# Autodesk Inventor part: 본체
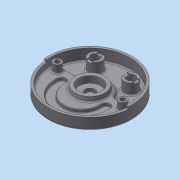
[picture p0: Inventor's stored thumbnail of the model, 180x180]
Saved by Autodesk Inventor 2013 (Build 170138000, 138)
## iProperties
Created: 2015-04
Part Number: 본체
Material: 일반
Document SubType Name: Modeling
Designer: Administrator
Density: 1 g/cm^3
Author: Administrator
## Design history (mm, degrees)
sketch "스케치1"
  geometry: C1 r 95 at (0, 0); 1 further point
  constraints: 1 centre point, 1 coincident
  dimensions: "d0" = 190 diameter of C1
extrude "돌출1" new body sketch "스케치1" distance "d1" = 32; taper "d2" = 0 deg
sketch "스케치2"
  geometry: L1 (-89.196, 12)-(-40.249, 12); L2 (40.249, 12)-(89.196, 12); C1 r 95 at (0, 0) reference; A1 r 90 centre (0, 0) between (89.196, 12) and (-89.196, 12); A2 r 42 centre (0, 0) between (40.249, 12) and (-40.249, 12)
  constraints: 4 end point, 4 point on circle, 2 centre point, 2 coincident, 2 horizontal
  dimensions: "d3" = 180 diameter of A1; "d4" = 84 diameter of A2; "d6" = 12 vertical distance of C1.centre L1.end; "d7" = 12 vertical distance of L2.end C1.centre
extrude "돌출2" cut sketch "스케치2" distance "d8" = 25; taper "d9" = 0 deg
fillet "모깎기1" dims "d10" = 10
sketch "스케치3"
  geometry: L1 (-47.117, 12)-(-76.916, 12) reference; L2 (76.916, 12)-(47.117, 12) reference; C1 r 95 at (0, 0) reference; C2 r 90 at (0, 0); A1 r 10 centre (-76.916, 22) between (-86.53, 24.75) and (-76.916, 12) reference; A2 r 90 centre (0, 0) between (86.53, 24.75) and (-86.53, 24.75) reference; A3 r 10 centre (76.916, 22) between (76.916, 12) and (86.53, 24.75) reference; A4 r 10 centre (47.117, 22) between (38.056, 17.769) and (47.117, 12) reference; A5 r 42 centre (0, 0) between (38.056, 17.769) and (-38.056, 17.769) reference; A6 r 10 centre (-47.117, 22) between (-47.117, 12) and (-38.056, 17.769) reference
  constraints: 1 centre point, 1 coincident
  dimensions: "d11" = 180 diameter of C2
extrude "돌출3" cut sketch "스케치3" distance "d12" = 18; taper "d13" = 0 deg
sketch "스케치6"
  geometry: C1 r 35 at (0, 0); A1 r 42 centre (0, 0) between (38.056, 17.769) and (-38.056, 17.769) reference
  constraints: 1 centre point, 1 coincident
  dimensions: "d34" = 70 diameter of C1
extrude "돌출4" join sketch "스케치6" distance "d35" = 10; taper "d36" = -10 deg
sketch "스케치7"
  geometry: C1 r 33.237 at (0, 0) reference; C2 r 25 at (0, 0)
  constraints: 1 centre point, 1 coincident
  dimensions: "d37" = 50 diameter of C2
extrude "돌출5" cut sketch "스케치7" distance "d38" = 15; taper "d39" = 0 deg
sketch "스케치8"
  geometry: C1 r 25 at (0, 0) reference; C2 r 11.5 at (0, 0)
  constraints: 1 centre point, 1 coincident
  dimensions: "d40" = 23 diameter of C2
extrude "돌출6" cut sketch "스케치8" stored distance "d41" = 15; taper "d42" = 0 deg
sketch "스케치9"
  geometry: C1 r 15 at (-40, 52); C2 r 15 at (40, 52); A1 r 90 centre (0, 0) between (86.53, 24.75) and (-86.53, 24.75) reference
  constraints: 2 centre point, 1 horizontal alignment
  dimensions: "d43" = 30 diameter of C1; "d44" = 30 diameter of C2; "d45" = 80 distance of C2.centre C1.centre; "d46" = 40 horizontal distance of C1.centre A1.centre; "d47" = 52 vertical distance of A1.centre C2.centre
extrude "돌출7" join sketch "스케치9" distance "d48" = 25; taper "d49" = 0 deg
sketch "스케치10"
  geometry: C1 r 15 at (0, 0) reference; C2 r 15 at (80, 0) reference; C3 r 10 at (0, 0); C4 r 10 at (80, 0); 1 further point
  constraints: 2 centre point, 2 coincident
  dimensions: "d50" = 20 diameter of C3; "d51" = 20 diameter of C4
extrude "돌출8" cut sketch "스케치10" stored distance "d52" = 25; taper "d53" = 0 deg
sketch "스케치11"
  geometry: C1 r 35 at (0, 0) reference; C2 r 9 at (-74, 0); C3 r 9 at (74, 0)
  constraints: 2 centre point, 2 horizontal alignment
  dimensions: "d54" = 18 diameter of C2; "d55" = 18 diameter of C3; "d56" = 148 distance of C3.centre C2.centre; "d57" = 74 distance of C2.centre C1.centre
extrude "돌출9" join sketch "스케치11" distance "d58" = 18; taper "d59" = 0 deg
sketch "스케치12"
  geometry: C1 r 9 at (-74, 0) reference; C2 r 10 at (40, 52) reference; C3 r 10 at (-40, 52) reference; C4 r 11.5 at (0, 0) reference; C5 r 95 at (0, 0) reference; C6 r 9 at (74, 0) reference; 2 further points
  constraints: 2 coincident
hole "구멍1" sketch "스케치12" at (-74, 0), (74, 0) diameter "d60" = 11; stored, may be unused: countersink angle "d64" = 90 deg, drill point angle "d66" = 0 deg; dims "d61" = 6, "d62" = 18, "d63" = 11, "d65" = 8
sketch "스케치13"
  geometry: L1 (-76.916, 12)-(-47.117, 12) reference; L2 (-59, -19)-(-41, -19); L3 (41, -19)-(59, -19); L4 (41, -19)-(41, -14); L5 (59, -19)-(59, -14); L6 (41, -14)-(59, -14); L7 (-59, -19)-(-59, -14); L8 (-41, -19)-(-41, -14); L9 (-41, -14)-(-59, -14); C1 r 35 at (0, 0) reference; A1 r 59 centre (0, -19) between (-59, -19) and (59, -19); A2 r 41 centre (0, -19) between (-41, -19) and (41, -19); A3 r 9 centre (50, -14) between (59, -14) and (41, -14); A4 r 9 centre (-50, -14) between (-41, -14) and (-59, -14)
  constraints: 16 end point, 8 point on circle, 4 centre point, 4 tangent, 2 midpoint, 2 parallel, 1 coincident, 1 collinear, 1 perpendicular, 1 vertical alignment
  dimensions: "d70" = 82 diameter of A2; "d72" = 19 distance of A1.centre C1.centre; "d75" = 5 distance of L4.end L3.start; "d76" = 5 distance of L5.end L3.end; "d79" = 59 radius of A1; "d80" = 5 distance of L7.end L2.start; "d81" = 5 distance of L8.end L2.end
extrude "돌출10" cut sketch "스케치13" distance "d83" = 7; taper "d84" = 0 deg
sketch "스케치16"
  geometry: L1 (0, 0)-(-112.328, 0); L2 (-89.658, -7.844)-(-94.638, -8.28); L3 (0, 0)-(105.461, 0); L4 (89.658, -7.844)-(94.638, -8.28); A1 r 95 centre (0, 0) between (-94.638, -8.28) and (94.638, -8.28) reference; A2 r 90 centre (0, 0) between (-89.658, -7.844) and (89.658, -7.844) reference
  constraints: 8 end point, 4 point on circle, 1 collinear, 1 horizontal
  dimensions: "d90" = 5 deg angle of L2 L1; "d91" = 5 deg angle of L4 L3; "d92" = 4.98097 horizontal distance of L2.start L2.end; "d93" = 4.98097 horizontal distance of L4.start L4.end
extrude "돌출12" cut sketch "스케치16" distance "d94" = 5; taper "d95" = 0 deg
fillet "모깎기2" dims "d96" = 0.3
fillet "모깎기3" dims "d97" = 5
chamfer "모따기1" distance "d99" = 1; stored, may be unused: second distance "d100" = 2, angle "d101" = 45 deg
fillet "모깎기5" dims "d102" = 1
fillet "모깎기6" dims "d103" = 3
chamfer "모따기2" distance "d104" = 1; stored, may be unused: second distance "d105" = 2, angle "d106" = 45 deg
sketch "스케치17"
  geometry: L1 (-6, 13.748)-(-6, 8); L2 (-6, -8)-(-6, -13.748); L3 (6, 13.748)-(6, 8); L4 (6, -8)-(6, -13.748); L5 (66.252, 6)-(72, 6); L6 (88, 6)-(93.748, 6); L7 (66.252, -6)-(72, -6); L8 (88, -6)-(93.748, -6); A1 r 10 centre (0, 0) between (-6, 8) and (-6, -8) reference; A2 r 15 centre (0, 0) between (-6, -13.748) and (6, -13.748) reference; A3 r 15 centre (80, 0) between (66.252, -6) and (66.252, 6) reference; A4 r 10 centre (80, 0) between (72, 6) and (88, 6) reference; 1 further point
  constraints: 16 end point, 16 point on circle, 12 parallel, 2 perpendicular, 2 vertical, 1 horizontal alignment, 1 vertical alignment
  dimensions: "d110" = 12 distance of L7.start L5.start; "d112" = 12 distance of L3.start L1.start
extrude "돌출13" cut sketch "스케치17" distance "d113" = 3; taper "d114" = 0 deg
fillet "모깎기7" dims "d115" = 3
sketch "스케치18"
  geometry: L1 (0, 0)-(0, -85.954); L2 (-36.062, -36.062)-(-50.912, -50.912); L3 (36.062, -36.062)-(50.912, -50.912); C1 r 12.5 at (0, 0) reference; A1 r 51 centre (0, 0) between (-36.062, -36.062) and (36.062, -36.062); A2 r 72 centre (0, 0) between (-50.912, -50.912) and (50.912, -50.912)
  constraints: 6 end point, 4 point on circle, 2 centre point, 2 coincident, 1 vertical
  dimensions: "d117" = 102 diameter of A1; "d120" = 72 radius of A2; "d121" = 21 distance of L3.start L3.end; "d122" = 21 distance of L2.start L2.end; "d123" = 45 deg angle of L1 L2; "d124" = 45 deg angle of L3 L1
extrude "돌출14" join sketch "스케치18" distance "d125" = 5; taper "d126" = 0 deg
fillet "모깎기8" dims "d127" = 5
fillet "모깎기9" dims "d128" = 3
sketch "스케치19"
  geometry: C1 r 68 at (0, 0); 1 further point
  constraints: 1 centre point, 1 coincident, 1 other
  dimensions: "d129" = 136 diameter of C1
feature "엠보싱1" sketch "스케치19" dims "d130" = 0.5, "d131" = 0
node "솔리드1"
node "투영된 루프1"
node "투영된 루프2"
other parameters: "d5" = 12, "d17" = 19, "d107" = 12, "d116" = 144, "d118" = 45 deg, "d119" = 45 deg
